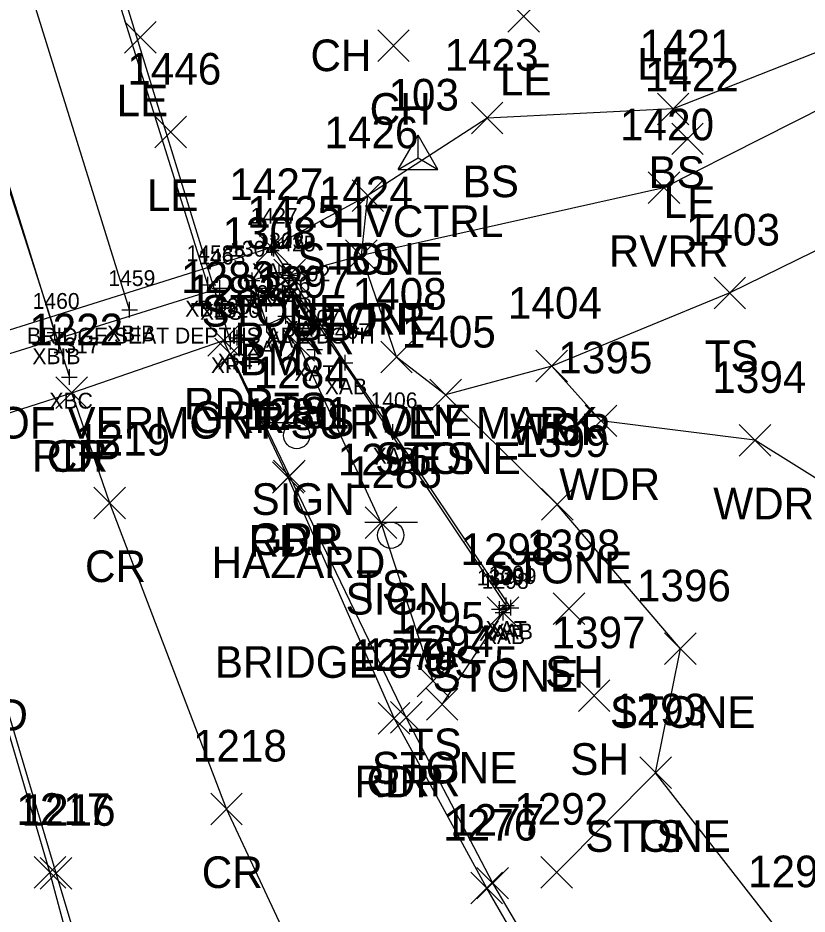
# Model space of a CAD drawing. Extents: x 1620157 to 1620595, y 115111 to 117885.
# Drawn here: x 1620342.3 to 1620392.2, y 115358.6 to 115415.3 of the extents above; entities that cross this region are included whole.
import ezdxf

# ---------------------------------------------------------------- set-up
doc = ezdxf.new("R2010")
doc.units = 0
for name, color, linetype in [('B_A', 7, 'Continuous'), ('B_C', 7, 'Continuous'), ('B_I', 7, 'Continuous'), ('B_TIC', 7, 'Continuous'), ('BB', 7, 'Continuous'), ('BELB', 7, 'Continuous'), ('BR', 7, 'Continuous'), ('BSE', 7, 'Continuous'), ('BSUBM', 7, 'Continuous'), ('C_A', 7, 'Continuous'), ('C_C', 7, 'Continuous'), ('C_I', 7, 'Continuous'), ('CPBM', 7, 'Continuous'), ('CPSM', 7, 'Continuous'), ('L_A', 7, 'Continuous'), ('L_I', 7, 'Continuous'), ('L_TIC', 7, 'Continuous'), ('LASF', 7, 'Continuous'), ('LAWA', 7, 'Continuous'), ('LAWE', 7, 'Continuous'), ('LELB', 7, 'Continuous'), ('P_A', 7, 'Continuous'), ('P_I', 7, 'Continuous'), ('P_TIC', 7, 'Continuous'), ('PET', 7, 'Continuous'), ('PRC', 7, 'Continuous'), ('R_A', 7, 'Continuous'), ('R_I', 7, 'Continuous'), ('R_TIC', 7, 'Continuous'), ('RGR', 7, 'Continuous'), ('S_A', 7, 'Continuous'), ('S_C', 7, 'Continuous'), ('S_I', 7, 'Continuous'), ('SSGN', 7, 'Continuous')]:
    doc.layers.add(name, color=color, linetype=linetype)

msp = doc.modelspace()

# ---------------------------------------------------------------- linework, layer by layer
at = {"layer": 'B_TIC'}
for p, q in [((1620358.361, 115400.738), (1620358.437, 115400.738)), ((1620358.829, 115399.162), (1620358.904, 115399.162)), ((1620357.101, 115398.659), (1620357.177, 115398.659)), ((1620359.488, 115398.989), (1620359.564, 115398.989)), ((1620354.305, 115398.372), (1620354.38, 115398.372)), ((1620355.07, 115398.165), (1620355.145, 115398.165)), ((1620349.358, 115396.802), (1620349.433, 115396.802)), ((1620360.464, 115397.095), (1620360.54, 115397.095)), ((1620359.233, 115396.404), (1620359.308, 115396.404)), ((1620358.037, 115395.852), (1620358.112, 115395.852)), ((1620344.63, 115395.358), (1620344.705, 115395.358)), ((1620355.74, 115394.792), (1620355.815, 115394.792)), ((1620356.168, 115395.033), (1620356.244, 115395.033)), ((1620361.072, 115394.291), (1620361.147, 115394.291)), ((1620362.989, 115393.449), (1620363.065, 115393.449)), ((1620345.541, 115392.547), (1620345.617, 115392.547)), ((1620366.013, 115389.074), (1620366.089, 115389.074)), ((1620373.186, 115378.107), (1620373.261, 115378.107)), ((1620372.759, 115377.874), (1620372.835, 115377.874)), ((1620372.99, 115377.653), (1620373.065, 115377.653)), ((1620373.484, 115377.958), (1620373.559, 115377.958))]:
    msp.add_line(p, q, dxfattribs=at)
for points in [[(1620358.358, 115400.238), (1620358.358, 115401.238)], [(1620357.858, 115400.738), (1620358.858, 115400.738)], [(1620358.825, 115398.662), (1620358.825, 115399.662)], [(1620357.098, 115398.159), (1620357.098, 115399.159)], [(1620358.325, 115399.162), (1620359.325, 115399.162)], [(1620359.485, 115398.489), (1620359.485, 115399.489)], [(1620354.301, 115397.872), (1620354.301, 115398.872)], [(1620355.066, 115397.665), (1620355.066, 115398.665)], [(1620356.598, 115398.659), (1620357.598, 115398.659)], [(1620358.985, 115398.989), (1620359.985, 115398.989)], [(1620353.801, 115398.372), (1620354.801, 115398.372)], [(1620354.566, 115398.165), (1620355.566, 115398.165)], [(1620360.461, 115396.595), (1620360.461, 115397.595)], [(1620348.854, 115396.802), (1620349.854, 115396.802)], [(1620349.354, 115396.302), (1620349.354, 115397.302)], [(1620359.229, 115395.904), (1620359.229, 115396.904)], [(1620359.961, 115397.095), (1620360.961, 115397.095)], [(1620358.033, 115395.352), (1620358.033, 115396.352)], [(1620358.729, 115396.404), (1620359.729, 115396.404)], [(1620344.626, 115394.858), (1620344.626, 115395.858)], [(1620357.533, 115395.852), (1620358.533, 115395.852)], [(1620344.126, 115395.358), (1620345.126, 115395.358)], [(1620355.736, 115394.292), (1620355.736, 115395.292)], [(1620356.165, 115394.533), (1620356.165, 115395.533)], [(1620355.236, 115394.792), (1620356.236, 115394.792)], [(1620355.665, 115395.033), (1620356.665, 115395.033)], [(1620361.068, 115393.791), (1620361.068, 115394.791)], [(1620360.568, 115394.291), (1620361.568, 115394.291)], [(1620362.986, 115392.949), (1620362.986, 115393.949)], [(1620362.486, 115393.449), (1620363.486, 115393.449)], [(1620345.538, 115392.047), (1620345.538, 115393.047)], [(1620345.038, 115392.547), (1620346.038, 115392.547)], [(1620366.01, 115388.574), (1620366.01, 115389.574)], [(1620365.51, 115389.074), (1620366.51, 115389.074)], [(1620372.682, 115378.107), (1620373.682, 115378.107)], [(1620372.756, 115377.374), (1620372.756, 115378.374)], [(1620372.986, 115377.153), (1620372.986, 115378.153)], [(1620373.182, 115377.607), (1620373.182, 115378.607)], [(1620373.48, 115377.458), (1620373.48, 115378.458)], [(1620372.256, 115377.874), (1620373.256, 115377.874)], [(1620372.486, 115377.653), (1620373.486, 115377.653)], [(1620372.98, 115377.958), (1620373.98, 115377.958)]]:
    msp.add_lwpolyline(points, dxfattribs=at)
at = {"layer": 'BB'}
for points in [[(1620354.301, 115398.372), (1620340.579, 115442.1)], [(1620349.354, 115396.802), (1620335.705, 115440.621)], [(1620344.626, 115395.358), (1620331.032, 115439.016)]]:
    msp.add_lwpolyline(points, dxfattribs=at)
at = {"layer": 'BELB'}
msp.add_lwpolyline([(1620336.951, 115419.174), (1620345.538, 115392.547)], dxfattribs=at)
at = {"layer": 'BR'}
msp.add_lwpolyline([(1620356.165, 115395.033), (1620355.736, 115394.792), (1620348.03, 115419.821)], dxfattribs=at)
at = {"layer": 'BSE'}
msp.add_lwpolyline([(1620355.066, 115398.165), (1620335.113, 115391.945)], dxfattribs=at)
at = {"layer": 'BSUBM'}
for points in [[(1620372.986, 115377.653), (1620373.48, 115377.958), (1620366.01, 115389.074), (1620362.986, 115393.449), (1620359.485, 115398.989), (1620358.358, 115400.738), (1620339.034, 115394.674), (1620334.564, 115393.214), (1620330.44, 115391.836), (1620330.552, 115389.649), (1620330.87, 115388.823), (1620331.045, 115384.876), (1620331.446, 115373.918), (1620332.004, 115369.254), (1620332.585, 115364.537)], [(1620372.756, 115377.874), (1620373.182, 115378.107), (1620360.461, 115397.095), (1620358.825, 115399.162), (1620357.098, 115398.659), (1620358.033, 115395.852), (1620359.229, 115396.404), (1620361.068, 115394.291)]]:
    msp.add_lwpolyline(points, dxfattribs=at)
at = {"layer": 'CPBM'}
for p, q in [((1620357.5, 115397.155), (1620357.5, 115398.155)), ((1620357.5, 115398.155), (1620358.5, 115398.155)), ((1620358.5, 115398.155), (1620358.5, 115397.155)), ((1620358.002, 115397.655), (1620358.002, 115397.655)), ((1620358.002, 115397.655), (1620358.002, 115397.655)), ((1620358.5, 115397.155), (1620357.5, 115397.155))]:
    msp.add_line(p, q, dxfattribs=at)
at = {"layer": 'CPSM'}
for p, q in [((1620366.358, 115405.679), (1620367.608, 115407.844)), ((1620368.858, 115405.679), (1620367.608, 115407.844)), ((1620367.608, 115406.4), (1620367.608, 115407.844)), ((1620366.358, 115405.679), (1620367.608, 115406.4)), ((1620367.608, 115406.4), (1620367.608, 115406.4)), ((1620367.608, 115406.4), (1620368.858, 115405.679)), ((1620366.358, 115405.679), (1620368.858, 115405.679))]:
    msp.add_line(p, q, dxfattribs=at)
at = {"layer": 'L_TIC'}
for points in [[(1620373.291, 115414.353), (1620375.291, 115416.353)], [(1620375.291, 115414.353), (1620373.291, 115416.353)], [(1620349.039, 115413.034), (1620351.039, 115415.034)], [(1620351.039, 115413.034), (1620349.039, 115415.034)], [(1620365.055, 115412.501), (1620367.055, 115414.501)], [(1620367.055, 115412.501), (1620365.055, 115414.501)], [(1620382.751, 115408.505), (1620384.751, 115410.505)], [(1620384.751, 115408.505), (1620382.751, 115410.505)], [(1620370.983, 115407.919), (1620372.983, 115409.919)], [(1620372.983, 115407.919), (1620370.983, 115409.919)], [(1620350.953, 115407.042), (1620352.953, 115409.042)], [(1620352.953, 115407.042), (1620350.953, 115409.042)], [(1620383.659, 115406.61), (1620385.659, 115408.61)], [(1620385.659, 115406.61), (1620383.659, 115408.61)], [(1620382.169, 115403.517), (1620384.169, 115405.517)], [(1620384.169, 115403.517), (1620382.169, 115405.517)], [(1620363.427, 115403.016), (1620365.427, 115405.016)], [(1620365.427, 115403.016), (1620363.427, 115405.016)], [(1620363.427, 115403.016), (1620365.427, 115405.016)], [(1620365.427, 115403.016), (1620363.427, 115405.016)], [(1620357.358, 115399.738), (1620359.358, 115401.738)], [(1620359.358, 115399.738), (1620357.358, 115401.738)], [(1620363.018, 115399.223), (1620365.018, 115401.223)], [(1620365.018, 115399.223), (1620363.018, 115401.223)], [(1620363.018, 115399.223), (1620365.018, 115401.223)], [(1620365.018, 115399.223), (1620363.018, 115401.223)], [(1620358.485, 115397.989), (1620360.485, 115399.989)], [(1620360.485, 115397.989), (1620358.485, 115399.989)], [(1620386.337, 115396.863), (1620388.337, 115398.863)], [(1620388.337, 115396.863), (1620386.337, 115398.863)], [(1620359.06, 115393.551), (1620361.06, 115395.551)], [(1620361.06, 115393.551), (1620359.06, 115395.551)], [(1620365.244, 115392.806), (1620367.244, 115394.806)], [(1620367.244, 115392.806), (1620365.244, 115394.806)], [(1620375.066, 115392.239), (1620377.066, 115394.239)], [(1620377.066, 115392.239), (1620375.066, 115394.239)], [(1620375.066, 115392.239), (1620377.066, 115394.239)], [(1620377.066, 115392.239), (1620375.066, 115394.239)], [(1620368.349, 115390.41), (1620370.349, 115392.41)], [(1620370.349, 115390.41), (1620368.349, 115392.41)], [(1620368.349, 115390.41), (1620370.349, 115392.41)], [(1620370.349, 115390.41), (1620368.349, 115392.41)], [(1620378.179, 115388.775), (1620380.179, 115390.775)], [(1620380.179, 115388.775), (1620378.179, 115390.775)], [(1620387.928, 115387.543), (1620389.928, 115389.543)], [(1620389.928, 115387.543), (1620387.928, 115389.543)], [(1620375.421, 115383.492), (1620377.421, 115385.492)], [(1620377.421, 115383.492), (1620375.421, 115385.492)], [(1620364.268, 115382.328), (1620366.268, 115384.328)], [(1620366.268, 115382.328), (1620364.268, 115384.328)], [(1620371.986, 115376.653), (1620373.986, 115378.653)], [(1620373.986, 115376.653), (1620371.986, 115378.653)], [(1620376.161, 115376.899), (1620378.161, 115378.899)], [(1620378.161, 115376.899), (1620376.161, 115378.899)], [(1620383.208, 115374.36), (1620385.208, 115376.36)], [(1620385.208, 115374.36), (1620383.208, 115376.36)], [(1620367.559, 115372.316), (1620369.559, 115374.316)], [(1620369.559, 115372.316), (1620367.559, 115374.316)], [(1620377.751, 115371.388), (1620379.751, 115373.388)], [(1620379.751, 115371.388), (1620377.751, 115373.388)], [(1620368.135, 115370.842), (1620370.135, 115372.842)], [(1620370.135, 115370.842), (1620368.135, 115372.842)], [(1620381.643, 115366.518), (1620383.643, 115368.518)], [(1620383.643, 115366.518), (1620381.643, 115368.518)], [(1620381.643, 115366.518), (1620383.643, 115368.518)], [(1620383.643, 115366.518), (1620381.643, 115368.518)], [(1620375.382, 115360.231), (1620377.382, 115362.231)], [(1620377.382, 115360.231), (1620375.382, 115362.231)]]:
    msp.add_lwpolyline(points, dxfattribs=at)
at = {"layer": 'LASF'}
for points in [[(1620376.382, 115361.231), (1620382.643, 115367.518), (1620384.208, 115375.36), (1620376.421, 115384.492), (1620369.349, 115391.41), (1620366.244, 115393.806), (1620364.018, 115400.223), (1620364.427, 115404.016), (1620358.358, 115400.738)], [(1620369.135, 115371.842), (1620372.986, 115377.653)]]:
    msp.add_lwpolyline(points, dxfattribs=at)
at = {"layer": 'LAWA'}
msp.add_lwpolyline([(1620479.837, 115302.474), (1620458.096, 115310.323), (1620439.099, 115318.773), (1620415.165, 115330.854), (1620411.081, 115337.589), (1620399.961, 115349.142), (1620402.296, 115374.401), (1620397.666, 115383.091), (1620388.928, 115388.543), (1620379.179, 115389.775), (1620376.066, 115393.239)], dxfattribs=at)
at = {"layer": 'LAWE'}
msp.add_lwpolyline([(1620449.964, 115358.032), (1620436.112, 115380.231), (1620427.899, 115395.847), (1620420.618, 115401.828), (1620402.043, 115406.007), (1620401.86, 115413.145), (1620395.518, 115410.757), (1620383.169, 115404.517), (1620364.018, 115400.223), (1620359.485, 115398.989)], dxfattribs=at)
at = {"layer": 'LELB'}
for points in [[(1620432.587, 115395.411), (1620422.71, 115405.327), (1620403.429, 115408.378), (1620404.584, 115416.965), (1620393.984, 115413.537), (1620383.751, 115409.505), (1620371.983, 115408.919), (1620364.427, 115404.016)], [(1620436.112, 115380.231), (1620426.996, 115389.197), (1620417.914, 115397.024), (1620408.342, 115396.95), (1620398.999, 115403.584), (1620387.337, 115397.863), (1620376.066, 115393.239), (1620369.349, 115391.41)], [(1620368.559, 115373.316), (1620365.268, 115383.328), (1620360.06, 115394.551)], [(1620399.961, 115349.142), (1620390.619, 115357.28), (1620382.643, 115367.518)]]:
    msp.add_lwpolyline(points, dxfattribs=at)
at = {"layer": 'P_TIC'}
for points in [[(1620354.301, 115393.861), (1620356.301, 115395.861)], [(1620356.301, 115393.861), (1620354.301, 115395.861)], [(1620354.301, 115393.861), (1620356.301, 115395.861)], [(1620356.301, 115393.861), (1620354.301, 115395.861)], [(1620344.687, 115390.553), (1620346.687, 115392.553)], [(1620346.687, 115390.553), (1620344.687, 115392.553)], [(1620344.687, 115390.553), (1620346.687, 115392.553)], [(1620346.687, 115390.553), (1620344.687, 115392.553)], [(1620358.386, 115385.192), (1620360.386, 115387.192)], [(1620360.386, 115385.192), (1620358.386, 115387.192)], [(1620347.096, 115383.578), (1620349.096, 115385.578)], [(1620349.096, 115383.578), (1620347.096, 115385.578)], [(1620365.092, 115369.963), (1620367.092, 115371.963)], [(1620367.092, 115369.963), (1620365.092, 115371.963)], [(1620354.485, 115364.231), (1620356.485, 115366.231)], [(1620356.485, 115364.231), (1620354.485, 115366.231)], [(1620343.694, 115360.164), (1620345.694, 115362.164)], [(1620345.694, 115360.164), (1620343.694, 115362.164)], [(1620370.951, 115359.23), (1620372.951, 115361.23)], [(1620372.951, 115359.23), (1620370.951, 115361.23)]]:
    msp.add_lwpolyline(points, dxfattribs=at)
at = {"layer": 'PET'}
for points in [[(1620562.045, 115139.537), (1620535.961, 115156.898), (1620508.491, 115175.945), (1620479.205, 115196.111), (1620451.098, 115216.616), (1620428.041, 115234.702), (1620407.201, 115256.439), (1620380.209, 115287.874), (1620366.182, 115309.187), (1620356.593, 115324.555), (1620350.492, 115341.932), (1620344.694, 115361.164), (1620336.512, 115388.614), (1620345.687, 115391.553), (1620355.301, 115394.861)], [(1620577.197, 115162.039), (1620550.221, 115180.342), (1620521.548, 115200.747), (1620501.474, 115215.644), (1620479.08, 115232.557), (1620460.808, 115248.092), (1620448.189, 115259.614), (1620427.721, 115280.564), (1620407.744, 115305.047), (1620395.056, 115322.869), (1620383.524, 115342.079), (1620378.465, 115348.988), (1620371.951, 115360.23), (1620366.092, 115370.963), (1620359.386, 115386.192), (1620355.301, 115394.861)]]:
    msp.add_lwpolyline(points, dxfattribs=at)
at = {"layer": 'PRC'}
msp.add_lwpolyline([(1620569.192, 115149.917), (1620542.761, 115168.022), (1620512.114, 115189.578), (1620491.048, 115205.01), (1620469.112, 115221.777), (1620461.731, 115227.824), (1620438.824, 115247.131), (1620418.591, 115266.65), (1620405.031, 115281.948), (1620392.881, 115297.861), (1620380.474, 115316.237), (1620370.644, 115332.813), (1620355.485, 115365.231), (1620348.096, 115384.578), (1620345.687, 115391.553)], dxfattribs=at)
at = {"layer": 'R_TIC'}
for points in [[(1620354.75, 115393.011), (1620356.75, 115395.011)], [(1620356.75, 115393.011), (1620354.75, 115395.011)], [(1620358.466, 115385.289), (1620360.466, 115387.289)], [(1620360.466, 115385.289), (1620358.466, 115387.289)], [(1620365.859, 115370.021), (1620367.859, 115372.021)], [(1620367.859, 115370.021), (1620365.859, 115372.021)], [(1620343.313, 115360.225), (1620345.313, 115362.225)], [(1620345.313, 115360.225), (1620343.313, 115362.225)], [(1620371.334, 115359.536), (1620373.334, 115361.536)], [(1620373.334, 115359.536), (1620371.334, 115361.536)]]:
    msp.add_lwpolyline(points, dxfattribs=at)
at = {"layer": 'RGR'}
for points in [[(1620479.271, 115300.405), (1620457.624, 115307.811), (1620437.199, 115314.771), (1620419.327, 115321.891), (1620405.307, 115328.344), (1620392.325, 115336.263), (1620384.188, 115342.415), (1620379.175, 115348.978), (1620372.334, 115360.536), (1620366.859, 115371.021), (1620359.466, 115386.289), (1620355.75, 115394.011)], [(1620346.982, 115317.888), (1620350.804, 115321.196), (1620352.683, 115325.401), (1620352.529, 115329.549), (1620349.57, 115341.57), (1620344.313, 115361.225), (1620336.401, 115388.033)]]:
    msp.add_lwpolyline(points, dxfattribs=at)
at = {"layer": 'SSGN'}
for p, q in [((1620358.278, 115389.68), (1620361.611, 115389.68)), ((1620359.925, 115388.847), (1620359.925, 115388.847)), ((1620364.233, 115383.377), (1620367.566, 115383.377)), ((1620365.88, 115382.543), (1620365.88, 115382.543))]:
    msp.add_line(p, q, dxfattribs=at)
for centre in [(1620359.925, 115388.847), (1620365.88, 115382.543)]:
    msp.add_circle(centre, 0.833, dxfattribs=at)

# ---------------------------------------------------------------- texts
at = {"layer": 'B_A'}
for s, p in [('XAB', (1620357.078, 115398.738)), ('XAT', (1620357.53, 115397.162)), ('XAB', (1620358.205, 115396.989)), ('XBIB', (1620352.872, 115396.372)), ('XAT', (1620355.803, 115396.659)), ('XBS', (1620353.807, 115396.165)), ('XBIB', (1620347.925, 115394.802)), ('XAT', (1620359.166, 115395.095)), ('XAT', (1620357.934, 115394.404)), ('XAT', (1620356.738, 115393.852)), ('XBIB', (1620343.197, 115393.358)), ('XRF', (1620354.925, 115393.033)), ('XRF', (1620354.496, 115392.792)), ('XAT', (1620359.773, 115392.291)), ('XAB', (1620361.706, 115391.449)), ('XBC', (1620344.274, 115390.547)), ('XAB', (1620364.73, 115387.074)), ('XAT', (1620371.887, 115376.107)), ('XAB', (1620372.201, 115375.958)), ('XAT', (1620371.461, 115375.874)), ('XAB', (1620371.707, 115375.653))]:
    msp.add_text(s, height=1, dxfattribs=at).set_placement(p)
at = {"layer": 'B_C'}
msp.add_text('BRIDGE SEAT DEPTHS ARE BOTH', height=1, dxfattribs=at).set_placement((1620342.862, 115394.665))
at = {"layer": 'B_I'}
for s, p in [('1427', (1620357.012, 115402.238)), ('1303', (1620357.439, 115400.662)), ('1425', (1620358.139, 115400.489)), ('1458', (1620352.955, 115399.872)), ('1304', (1620355.712, 115400.159)), ('1463', (1620353.696, 115399.665)), ('1459', (1620348.004, 115398.302)), ('1302', (1620359.075, 115398.595)), ('1306', (1620357.816, 115397.904)), ('1305', (1620356.648, 115397.352)), ('1460', (1620343.213, 115396.858)), ('1309', (1620354.775, 115396.533)), ('1310', (1620354.63, 115396.292)), ('1307', (1620359.683, 115395.791)), ('1407', (1620361.6, 115394.949)), ('1317', (1620344.475, 115394.047)), ('1406', (1620364.596, 115390.574)), ('1300', (1620371.327, 115379.374)), ('1301', (1620372.08, 115379.607)), ('1299', (1620372.13, 115379.458)), ('1298', (1620371.64, 115379.153))]:
    msp.add_text(s, height=1, dxfattribs=at).set_placement(p)
at = {"layer": 'C_A'}
for s, p in [('HVCTRL', (1620362.301, 115401.4)), ('BM', (1620356.317, 115392.655))]:
    msp.add_text(s, height=2, dxfattribs=at).set_placement(p)
at = {"layer": 'C_C'}
msp.add_text('STATE OF VERMONT SURVEY MARK', height=2, dxfattribs=at).set_placement((1620331.593, 115388.655))
at = {"layer": 'C_I'}
for s, p in [('103', (1620365.735, 115409.4)), ('1308', (1620355.231, 115400.655))]:
    msp.add_text(s, height=2, dxfattribs=at).set_placement(p)
at = {"layer": 'L_A'}
for s, p in [('CH', (1620360.8, 115411.89)), ('LE', (1620381.484, 115411.344)), ('LE', (1620372.779, 115410.353)), ('LE', (1620348.528, 115409.034)), ('CH', (1620364.543, 115408.501)), ('BS', (1620382.192, 115404.505)), ('BS', (1620370.424, 115403.919)), ('LE', (1620350.442, 115403.042)), ('LE', (1620383.147, 115402.61)), ('RVRR', (1620379.681, 115399.517)), ('STONE', (1620359.971, 115399.016)), ('BS', (1620362.868, 115399.016)), ('STONE', (1620353.901, 115395.738)), ('STONE', (1620359.562, 115395.223)), ('RVRR', (1620360.53, 115395.223)), ('RVRR', (1620355.997, 115393.989)), ('TS', (1620385.747, 115392.863)), ('TS', (1620358.47, 115389.551)), ('STONE', (1620361.788, 115388.806)), ('WDR', (1620373.429, 115388.239)), ('TS', (1620374.476, 115388.239)), ('STONE', (1620364.893, 115386.41)), ('TS', (1620367.759, 115386.41)), ('WDR', (1620376.541, 115384.775)), ('WDR', (1620386.29, 115383.543)), ('STONE', (1620371.965, 115379.492)), ('TS', (1620363.677, 115378.328)), ('STONE', (1620368.53, 115372.653)), ('SH', (1620375.649, 115372.899)), ('STONE', (1620379.751, 115370.36)), ('TS', (1620366.969, 115368.316)), ('SH', (1620377.239, 115367.388)), ('STONE', (1620364.679, 115366.842)), ('STONE', (1620378.187, 115362.518)), ('TS', (1620381.053, 115362.518))]:
    msp.add_text(s, height=2, dxfattribs=at).set_placement(p)
at = {"layer": 'L_I'}
for s, p in [('1421', (1620381.626, 115412.505)), ('1423', (1620369.291, 115411.919)), ('1446', (1620349.206, 115411.042)), ('1422', (1620381.966, 115410.61)), ('1420', (1620380.39, 115407.517)), ('1426', (1620361.679, 115407.016)), ('1426', (1620361.679, 115407.016)), ('1427', (1620355.665, 115403.738)), ('1424', (1620361.326, 115403.223)), ('1424', (1620361.326, 115403.223)), ('1425', (1620356.792, 115401.989)), ('1403', (1620384.566, 115400.863)), ('1297', (1620357.368, 115397.551)), ('1408', (1620363.473, 115396.806)), ('1404', (1620373.295, 115396.239)), ('1404', (1620373.295, 115396.239)), ('1405', (1620366.578, 115394.41)), ('1405', (1620366.578, 115394.41)), ('1395', (1620376.486, 115392.775)), ('1394', (1620386.235, 115391.543)), ('1399', (1620373.721, 115387.492)), ('1296', (1620362.52, 115386.328)), ('1298', (1620370.294, 115380.653)), ('1398', (1620374.468, 115380.899)), ('1396', (1620381.46, 115378.36)), ('1295', (1620365.866, 115376.316)), ('1397', (1620376.058, 115375.388)), ('1294', (1620366.443, 115374.842)), ('1293', (1620379.951, 115370.518)), ('1293', (1620379.951, 115370.518)), ('1292', (1620373.69, 115364.231)), ('1291', (1620388.493, 115360.28))]:
    msp.add_text(s, height=2, dxfattribs=at).set_placement(p)
at = {"layer": 'P_A'}
for s, p in [('RDP', (1620352.789, 115389.861)), ('RDP', (1620352.789, 115389.861)), ('RDP', (1620343.175, 115386.553)), ('CR', (1620344.12, 115386.553)), ('RDP', (1620356.874, 115381.192)), ('CR', (1620346.529, 115379.578)), ('RDP', (1620363.58, 115365.963)), ('CR', (1620353.918, 115360.231))]:
    msp.add_text(s, height=2, dxfattribs=at).set_placement(p)
at = {"layer": 'P_I'}
for s, p in [('1283', (1620352.608, 115397.861)), ('1283', (1620352.608, 115397.861)), ('1222', (1620342.994, 115394.553)), ('1222', (1620342.994, 115394.553)), ('1280', (1620356.606, 115389.192)), ('1219', (1620345.963, 115387.578)), ('1279', (1620363.391, 115373.963)), ('1218', (1620353.359, 115368.231)), ('1216', (1620342.513, 115364.164)), ('1276', (1620369.203, 115363.23))]:
    msp.add_text(s, height=2, dxfattribs=at).set_placement(p)
at = {"layer": 'R_A'}
for p in [(1620353.238, 115389.011), (1620356.954, 115381.289), (1620364.347, 115366.021)]:
    msp.add_text('GRR', height=2, dxfattribs=at).set_placement(p)
at = {"layer": 'R_I'}
for s, p in [('1282', (1620353.057, 115397.011)), ('1281', (1620357.34, 115389.289)), ('1278', (1620364.166, 115374.021)), ('1217', (1620342.187, 115364.225)), ('1277', (1620369.641, 115363.536))]:
    msp.add_text(s, height=2, dxfattribs=at).set_placement(p)
at = {"layer": 'S_A'}
for p in [(1620357.063, 115383.827), (1620363.018, 115377.523)]:
    msp.add_text('SIGN', height=2, dxfattribs=at).set_placement(p)
at = {"layer": 'S_C'}
for s, p in [('HAZARD', (1620354.543, 115379.827)), ('BRIDGE 5 US 5', (1620354.742, 115373.523)), ('HAZARD', (1620331.921, 115370.175))]:
    msp.add_text(s, height=2, dxfattribs=at).set_placement(p)
at = {"layer": 'S_I'}
for s, p in [('1284', (1620357.212, 115391.827)), ('1285', (1620363.167, 115385.523))]:
    msp.add_text(s, height=2, dxfattribs=at).set_placement(p)

doc.saveas('drawing.dxf')
